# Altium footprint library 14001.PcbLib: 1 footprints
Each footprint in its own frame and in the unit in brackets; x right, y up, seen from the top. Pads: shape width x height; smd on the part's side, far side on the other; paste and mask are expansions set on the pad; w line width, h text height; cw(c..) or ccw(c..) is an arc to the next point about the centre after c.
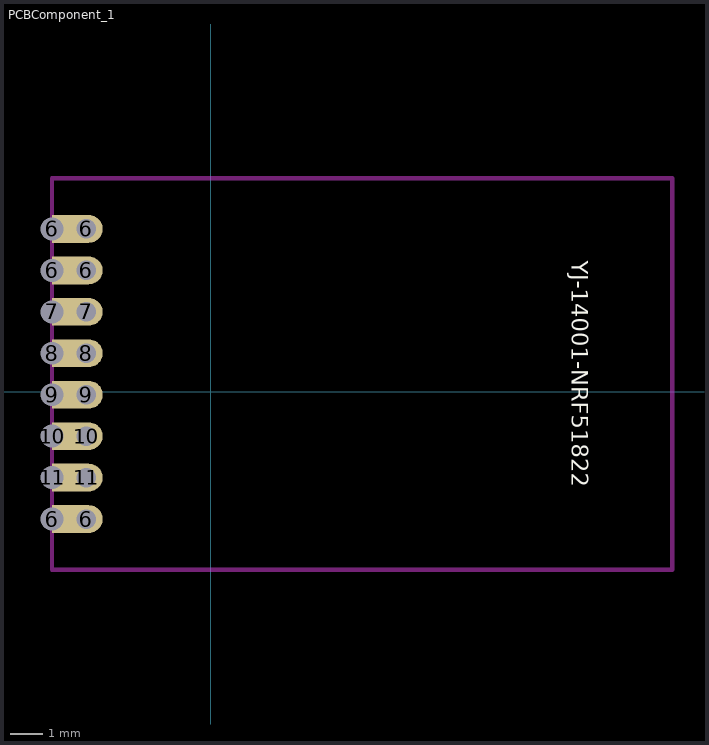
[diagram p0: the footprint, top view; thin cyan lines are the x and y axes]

## PCBComponent_1 [mm]
pads (16):
  rect 1x0.85 hole 0.7 copper offset 0.5,0: 6(-4.868,-3.908) 6(-4.868,3.712) 6(-4.868,4.982) 7(-4.868,2.442) 8(-4.868,1.172) 9(-4.868,-0.098) 10(-4.868,-1.368) 11(-4.868,-2.638)
  oval 1x0.85 hole 0.6: 6(-3.818,-3.908) 6(-3.818,3.712) 6(-3.818,4.982) 7(-3.818,2.442) 8(-3.818,1.172) 9(-3.818,-0.098) 10(-3.818,-1.368) 11(-3.818,-2.638)
Top Overlay:
  text "YJ-14001-NRF51822" at 11.062,4.002 h0.5
Bottom Overlay:
  text "VDD" at -3.018,4.622 h0.5
  text "P0.00" at -2.988,3.292 h0.5
  text "P0.01" at -2.988,1.992 h0.5
  text "P0.09" at -3.018,0.822 h0.5
  text "P0.11" at -3.038,-0.578 h0.5
  text "SWD" at -3.038,-1.698 h0.5
  text "SCLK" at -3.038,-3.048 h0.5
  text "GND" at -3.038,-4.288 h0.5
Keep-Out Layer:
  lines w0.127: -4.868,-5.463 -4.868,6.537 14.132,6.537 14.132,-5.463 -4.868,-5.463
